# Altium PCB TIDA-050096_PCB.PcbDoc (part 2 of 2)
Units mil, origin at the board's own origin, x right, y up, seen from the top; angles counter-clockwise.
Board outline 3810 x 5470 mil, 4 copper layers (Top Layer, Layer 1, Layer 2, Bottom Layer), stack 70.356 mil thick; 143 components, 52 nets, 310 pads, 92 vias.
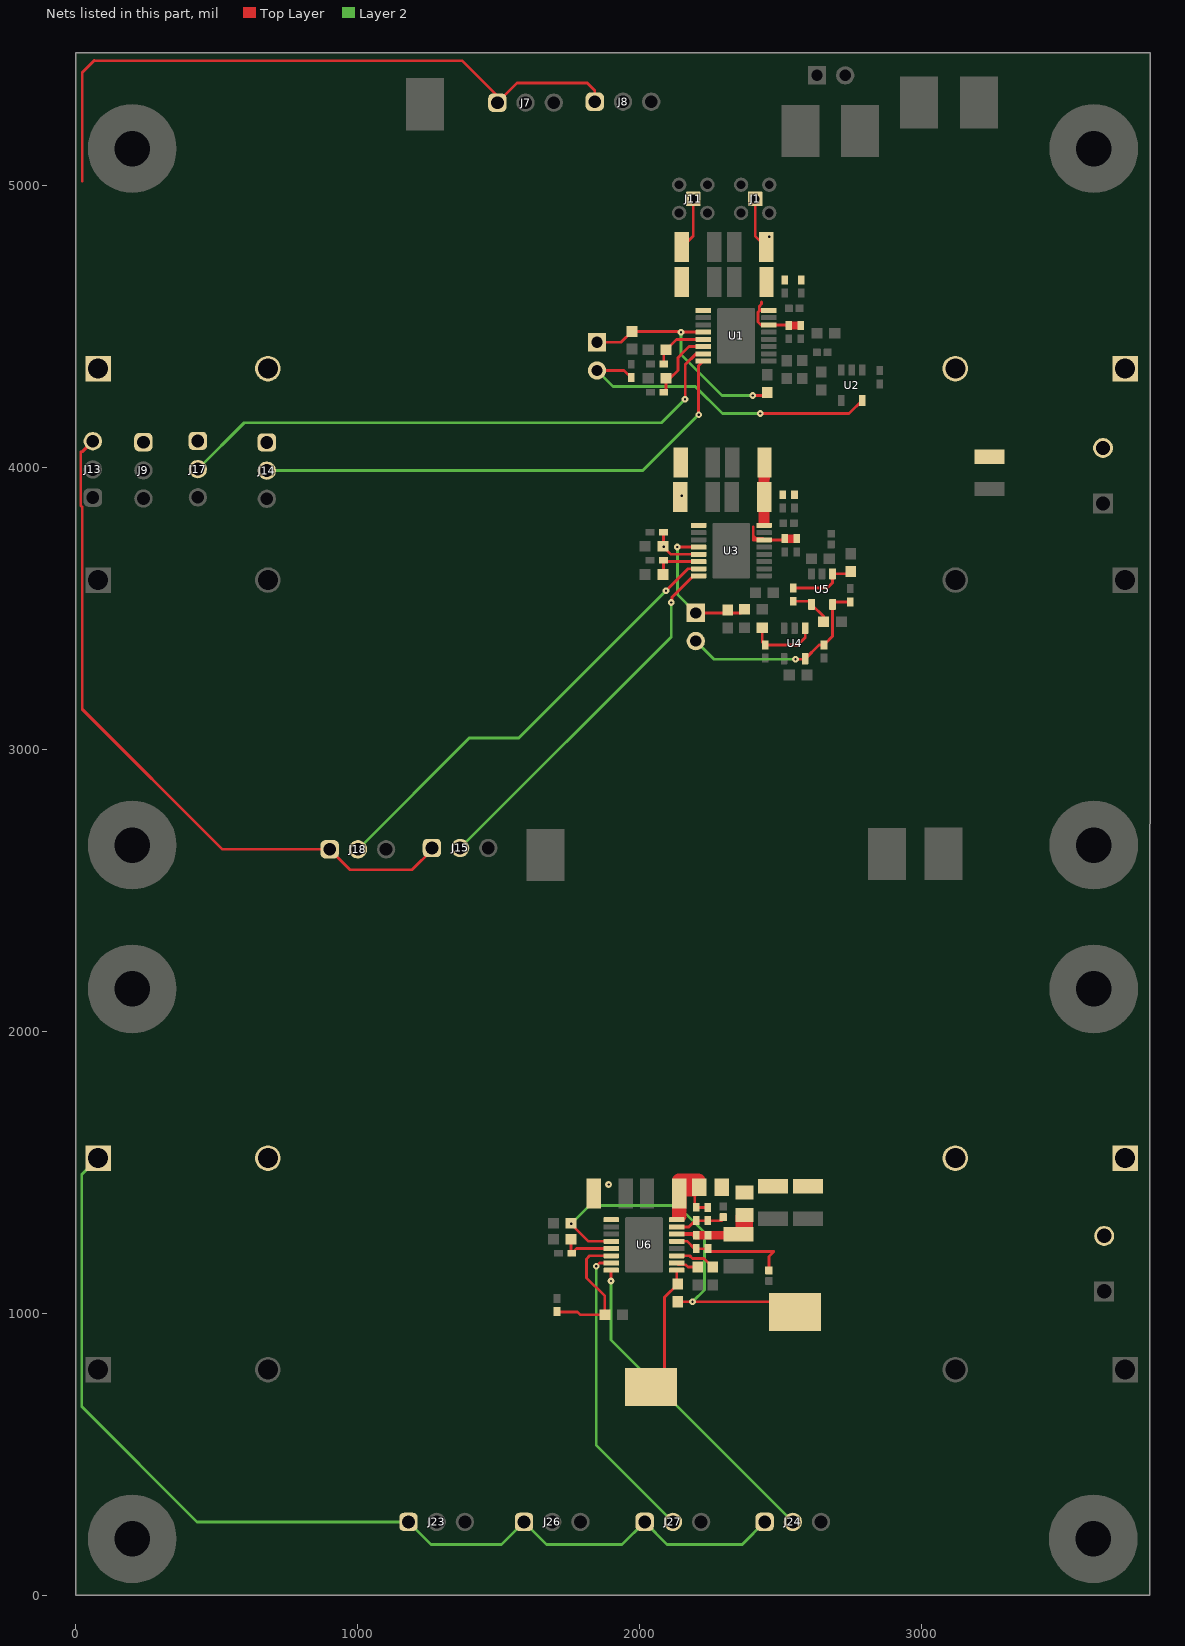
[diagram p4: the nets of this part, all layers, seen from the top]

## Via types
v1: diameter 24, hole 8, Top Layer to Bottom Layer, tented both sides, 47 vias
v2: diameter 19.68, hole 7.87, Top Layer to Bottom Layer, tented both sides, 36 vias
v3: diameter 19.68, hole 7.87, Top Layer to Bottom Layer, 9 vias

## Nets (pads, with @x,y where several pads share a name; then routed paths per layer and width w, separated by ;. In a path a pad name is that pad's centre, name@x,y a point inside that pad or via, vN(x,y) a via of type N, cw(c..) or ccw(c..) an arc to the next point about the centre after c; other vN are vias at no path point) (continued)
NetC11_2: C11.2 R13.1 U4.1 | length 251
  Top Layer w10: R13.1@2434.18,3431.17 2434.18,3380.72 C11.2@2444.63,3370.27 2560.74,3370.27 2586.59,3396.13 U4.1@2586.59,3429.28
NetC25_1: C25.1 R21.2 U5.4 | length 148.4
  Top Layer w10: C25.1@2544.49,3524.76 2598.09,3524.76 U5.4@2608.91,3513.94 2652.22,3470.63 R21.2@2652.22,3452.35
NetC25_2: C25.2 R24.1 U5.1 | length 247.1
  Top Layer w10: C25.2@2544.49,3572.01 2665.34,3572.01 2683.72,3590.38 U5.1@2683.72,3622.2 2740.42,3622.2 R24.1@2748.75,3630.54
NetC27_2: C27.2 R27.2 R34.2 U6.13 | length 433.1
  Top Layer w10: U6.13@2131.23,1254.98 2168.67,1254.98 2195.09,1228.57 2235.09,1228.57 2244.67,1218.98 2475.24,1218.98 2457.86,1201.6 R34.2@2457.86,1152.05
NetC28_2: C28.2 R28.2 R35.2 U6.15 | length 174.7
  Top Layer w10: U6.15@2131.23,1306.16 2173.52,1306.16 2195.1,1327.75 2235.78,1327.75 2236.32,1328.29 2289.29,1328.29 R35.2@2294.58,1333.58
NetC34_2: C34.2 R31.2 U6.6 | length 492.3
  Top Layer w10: R31.2@1706.39,1005.55 1706.39,1004.7 1779.25,1004.7 1789.61,994.33 C34.2@1876.09,994.33 1876.09,1060.66 1811.33,1125.42 1811.33,1192.8 1822.33,1203.8 U6.6@1898.95,1203.8
NetC35_2: C35.2 R32.2 U6.5 | length 206.2
  Top Layer w10: R32.2@1753.09,1206.57 R32.2@1758.71,1212.19 ; C35.2@1756.58,1262.19 1756.58,1214.31 R32.2@1758.71,1212.19 ; U6.5@1898.95,1229.39 1775.91,1229.39 R32.2@1758.71,1212.19
NetR29_2: R29.2 TP10.1 U6.9 | length 454.8
  Top Layer w10: TP10.1@2039.58,738.95 2088.11,787.47 2088.11,1056.7 R29.2@2135.09,1103.68 2131.23,1107.54 U6.9@2131.23,1152.62
NetR30_2: R30.2 U6.11 | length 143.8
  Top Layer w10: U6.11@2131.23,1203.8 2177.26,1203.8 2187.06,1194 2228.19,1194 2258.38,1163.81 R30.2@2258.38,1163.68
NetR33_2: R33.2 U6.10 | length 79.9
  Top Layer w10: U6.10@2131.23,1178.21 2137.33,1172.11 2162.05,1172.11 2170.48,1163.68 R33.2@2205.09,1163.68
SNS_EN1: J14.2 U1.8 | length 1810.9
  Top Layer w10: v1(2208.78,4186.51) 2208.78,4360.28 U1.8@2225.45,4376.95
  Layer 2 w10: J14.2@677.35,3988.19 2010.46,3988.19 v1(2208.78,4186.51)
SNS_EN2: J15.2 U3.8 | length 1325.8
  Top Layer w10: v1(2111.47,3520.76) 2114.15,3523.44 2114.15,3539 2189.74,3614.6 U3.8@2208.44,3614.6
  Layer 2 w10: J15.2@1362.81,2650.02 2111.47,3398.68 v1(2111.47,3520.76)
SNS_EN_Rb: J24.2 U6.8 | length 1160.5
  Top Layer w10: v1(1897.55,1114.37) 1897.55,1151.22 U6.8@1898.95,1152.62
  Layer 2 w10: v1(1897.55,1114.37) 1897.55,905.39 J24.2@2542.93,260
SNS_P: C10.2 R8.2 U1.5 | length 201
  Top Layer w10: R8.2@2085.21,4366.51 2085.21,4408.64 C10.2@2093.09,4416.51 2130.29,4453.72 2188.05,4453.72 U1.5@2225.45,4453.72
SNS_S1: C9.2 R7.2 U1.6 | length 258.2
  Top Layer w10: R7.2@2085.21,4266.51 2093.09,4274.39 C9.2@2093.09,4316.51 2108.22,4316.51 2135.13,4343.43 2135.13,4388.33 2162.55,4415.75 2174.93,4428.13 U1.6@2225.45,4428.13
SNS_S2: C24.2 R19.2 U3.5 | length 188.2
  Top Layer w10: C24.2@2081.94,3719.79 2084.07,3721.92 R19.2@2084.07,3769.79 ; C24.2@2082.93,3719.79 2111.35,3691.37 U3.5@2208.44,3691.37
  other v1: 2084.89,3717.82
SNS_S3: C23.2 R18.2 U3.6 | length 176.9
  Top Layer w10: C23.2@2081.94,3619.79 2084.07,3621.92 R18.2@2084.07,3669.79 2088.08,3665.78 U3.6@2208.44,3665.78
SNS_SEL1: J17.2 U1.7 | length 2033
  Top Layer w10: v1(2160.28,4241.53) 2161.5,4242.75 2161.5,4363.92 2200.11,4402.54 U1.7@2225.45,4402.54
  Layer 2 w10: J17.2@432.84,3993.49 597.42,4158.07 2076.82,4158.07 v1(2160.28,4241.53)
SNS_SEL2: J18.2 U3.7 | length 1620.5
  Top Layer w10: v1(2093.09,3562.42) 2170.85,3640.19 U3.7@2208.44,3640.19 U3.7@2208.24,3640.38
  Layer 2 w10: J18.2@1000.42,2645.17 1395.25,3040 1570.67,3040 v1(2093.09,3562.42)
SNS_SEL_Rb: J27.2 U6.7 | length 1076.9
  Top Layer w10: v1(1845.93,1166.64) 1857.51,1178.21 U6.7@1898.95,1178.21
  Layer 2 w10: v1(1845.93,1166.64) 1845.93,531.6 J27.2@2117.53,260
VCC_1: C8.2 J3.1 R5.1 U1.4 | length 843.1
  Top Layer w10: J3.1@1848.44,4443.21 1933.51,4443.21 C8.2@1972.39,4482.1 2143.76,4482.1 v1(2146.55,4479.31) U1.4@2225.45,4479.31 ; v1(2400.29,4254.52) 2441.09,4254.52 R5.1@2451.59,4265.02
  Layer 2 w10: v1(2146.55,4479.31) 2146.55,4400.19 2292.22,4254.52 v1(2400.29,4254.52)
VCC_1_out: C7.1 J3.2 U2.5 | length 1154.6
  Top Layer w10: J3.2@1848.44,4343.21 1944.39,4343.21 C7.1@1969.44,4318.17 ; v1(2427.57,4190.47) 2742.07,4190.47 U2.5@2788.99,4237.4
  Layer 2 w10: J3.2@1848.44,4343.21 1905.12,4286.53 2196.77,4286.53 2292.83,4190.47 v1(2427.57,4190.47)
VCC_2: C22.1 J12.1 R16.1 U3.4 | length 537.7
  Top Layer w10: v1(2133.28,3716.96) U3.4@2208.44,3716.96 ; J12.1@2198.61,3483.65 2358.04,3483.65 R16.1@2371.19,3496.8 ; C22.1@2302.39,3503.64 C22.1@2312.39,3493.64 ; R16.1@2381.65,3496.8 R16.1@2381.65,3506.8
  Layer 2 w10: v1(2133.28,3716.96) 2133.28,3548.98 J12.1@2198.61,3483.65
VCC_2_out: C20.1 C21.1 J12.2 U4.5 U5.5 | length 725
  Top Layer w10: v1(2552.3,3319.17) 2584.75,3319.17 U4.5@2586.59,3321.01 2635.87,3370.29 C20.1@2653.07,3370.29 2683.72,3400.94 U5.5@2683.72,3513.94 2692.44,3522.66 C21.1@2746.41,3522.66
  Layer 2 w10: J12.2@2198.61,3383.65 2263.09,3319.17 v1(2552.3,3319.17)
VCC_3: C33.1 R29.1 TP9.1 U6.4 | length 1400.5
  Top Layer w10: v1(1756.58,1316.99) 1818.59,1254.98 U6.4@1898.95,1254.98 ; R29.1@2135.09,1040.69 v1(2187.06,1040.69) 2513.48,1040.69 TP9.1@2550,1004.17
  Layer 2 w10: v1(1756.58,1316.99) 1821.23,1381.64 2134.42,1381.64 2229.42,1286.64 2229.42,1083.05 v1(2187.06,1040.69)
VIN: C12.1 C13.1 C14.1 C15.1 J4.1 J4.2 J7.1 J8.1 J9.1 J11.1 J13.3 J14.1 J15.1 J17.1 J18.1 U1.1 U3.1 | length 5050.8
  Top Layer w10: 22.91,5014.41 22.91,5400.39 65.18,5442.66 1371.2,5441.02 1495,5317.22 J7.1@1495,5293.09 1564.51,5362.59 1813.85,5362.59 1840.57,5335.88 J8.1@1840.57,5296.49 ; J13.3@58.8,4092.49 J13.3@60.33,4092.49 22.91,4055.08 17.21,4055.08 17.21,3865.12 22.91,3859.42 22.91,3142.09 519.83,2645.17 J18.1@900.42,2645.17 972.78,2572.8 1192.24,2572.8 1262.81,2643.38 J15.1@1262.81,2650.02 ; C13.1@2149.5,4780.71 2189.66,4820.87 J11.1@2189.66,4951.97
  other v1: 2149.3,3898.96
VIN2: C26.1 J19.1 J19.2 J23.1 J24.1 J26.1 J27.1 U6.1 | length 3695.1
  Layer 2 w10: J19.1@78.82,1550 21.03,1492.21 21.03,668.97 430,260 J23.1@1179.75,260 1259.94,179.82 1509.29,179.82 J26.1@1589.47,260 1669.65,179.82 1937.35,179.82 J27.1@2017.53,260 2097.15,180.38 2363.31,180.38 J24.1@2442.93,260
  other v1: 1889.55,1456.89
VOUT: C2.1 C3.1 C4.1 C5.1 C6.1 C16.1 C17.1 C18.1 C19.1 J1.1 J2.2 J5.1 J5.2 R3.1 R4.1 R14.1 R15.1 U1.14 U1.16 U3.14 U3.16 | length 1040
  Top Layer w10: J1.1@2409.22,4951.97 2409.22,4820.21 C5.1@2449,4780.44 ; U1.14@2431.62,4503.63 2419.54,4515.7 2419.54,4549.63 2423.55,4553.64 ; 2432.12,4585.65 2432.12,4578.91 2423.55,4570.34 2423.55,4553.64 ; U1.14@2457.73,4504.9 2568.39,4504.9 R3.1@2570.36,4502.93 ; U1.16@2457.73,4556.08 2429.14,4556.08 2427.57,4557.65 2423.55,4553.64 ; C16.1@2510.72,3747.23 C16.1@2513.55,3747.23 ; 2536.33,3747.17 R14.1@2556.14,3747.12 ; R14.1@2556.49,3747.47 R14.1@2556.14,3747.12 ; R14.1@2561.06,3747.11 2556.49,3747.12 R14.1@2556.14,3747.12 ; 2402.53,3756.02 2402.53,3788.34 2402.14,3788.73 2402.14,3756.41 2402.53,3756.02 ; 2402.53,3756.02 2402.53,3742.55 U3.14@2440.72,3742.55 ; 2402.53,3756.02 2409.9,3748.65 2434.62,3748.65 U3.14@2440.72,3742.55 ; U3.14@2440.72,3742.55 2551.57,3742.55 R14.1@2556.14,3747.12
  Top Layer w30: C16.1@2517.08,3747.38 R14.1@2551.07,3747.38 ; C3.1@2530.95,4502.84 R3.1@2564.94,4502.84
  Top Layer w40: 2440.39,3805.25 2440.92,3893.89 2441.65,4017.67 C18.1@2441.79,4040.58
  other v1: 2458.84,4817.4
VOUT1_Rb: C28.1 C29.1 R25.1 R28.1 U6.16 | length 430.8
  Top Layer w10: C29.1@2131.23,1415.91 2134.42,1419.11 C29.1@2139.91,1424.59 2154.67,1439.36 C29.1@2155.16,1439.84 ; R25.1@2207.95,1439.84 2195.1,1427 2195.1,1374.99 2235.78,1374.99 C28.1@2236.32,1375.54
  Top Layer w40: 2134.42,1344.17 2134.42,1419.11 C29.1@2134.42,1428.33 ; 2144.84,1342.98 C29.1@2144.84,1427.14
  Top Layer w50: C29.1@2139.78,1471.2 R25.1@2207.33,1471.2 ; C29.1@2145.6,1439.36 2154.67,1439.36 R25.1@2195.09,1439.36
VOUT2_Rb: C27.1 C32.1 R26.1 R27.1 U6.14 | length 336.8
  Top Layer w10: R27.1@2230.32,1280.57 2234.21,1276.69 R27.1@2235.09,1275.81
  Top Layer w15: U6.14@2131.23,1280.57 R27.1@2230.32,1280.57
  Top Layer w30: C27.1@2200.44,1276.69 2234.21,1276.69 C32.1@2300.45,1276.69
  Top Layer w40: C32.1@2359.89,1276.29 R26.1@2359.89,1342.4 ; R26.1@2370.99,1346.82 R26.1@2375.99,1341.82 ; C32.1@2381.18,1282.71 R26.1@2381.18,1340.47
VOUT_Rb: C30.1 C31.1 J20.1 J20.2 J25.2 R25.2 R26.2
pads on no net: H1.0 H2.0 H3.0 H4.0 H5.0 H6.0 H7.0 H8.0 U1.17@2341.59,4466.51 U3.17@2324.58,3704.16 U6.17@2015.09,1242.19

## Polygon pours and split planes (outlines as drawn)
GND on Layer 1 "LAYER_1_GND_P034" (solid, remove dead copper, pour order 34): -1.93,5470 3806.22,5470 3806.22,2480 -1.93,2480
GND2 on Layer 1 "LAYER_1_GND2_P027" (solid, remove dead copper, pour order 27): 5.27,2301.76 3815.27,2301.76 3815.27,3.49 3813.54,1.76 5.27,1.76
VOUT on Top Layer "Top Layer-VOUT" (solid, remove dead copper, pour order 16): 2372.61,3725.99 2869.81,3725.99 3113.82,3970 3800.23,3970 3800.23,4840.12 3809.81,4840 3808.11,4841.7 3808.11,4858.82 3809.81,4860.52 3808.11,4860.52 3808.11,5028.47 2661.33,5028.47 2493.38,4860.52 2385.14,4860.52 2385.14,4604.86 2383.95,4603.68 2409.22,4578.41 2409.22,4545.35 2413.11,4493.21 2744.34,4493.21 2890,4347.56 2890,4276.4 2783.6,4170 2372.61,4170
VIN on Top Layer "Top Layer-VIN" (solid, remove dead copper, pour order 17): 0,4039.1 798.36,4039.1 1079.66,3757.8 2255.45,3757.8 2254.34,3758.9 2254.34,3812.43 2245.13,3812.43 2214.62,3842.93 2214.62,4170 1790.47,4170 1735.16,4225.31 1735.16,4470.17 1784.14,4519.15 2273.52,4519.15 2273.52,4565.53 2221.51,4617.54 2221.51,4859.74 2221.07,4860.18 2218.05,4857.16 2101.78,4857.16 1938.94,5020 0,5020 0,4838.37
GND on Top Layer "TOP_LAYER_GND_P043" (solid, remove dead copper, pour order 43): -1.77,5470 3806.37,5470 3806.37,2480 -1.77,2480
GND2 on Top Layer "TOP_LAYER_GND2_P044" (solid, remove dead copper, pour order 44): 0,2300 3810,2300 3810,1.73 3808.27,0 0,0
VOUT_Rb on Top Layer "TOP_LAYER_VOUT_RB_P026" (solid, remove dead copper, pour order 26): 3803.66,1200 3803.66,2300 2259.96,2300 2259.96,1394.21 2266.88,1401.13 2658.08,1401.13 2859.21,1200 3808.24,1200
VIN2 on Top Layer "TOP_LAYER_VIN2_P021" (solid, remove dead copper, pour order 21): 0,1300 22.58,1322.58 1907,1322.58 1907,2300 -3.66,2300 -3.66,1300
no net on Top Layer "TOP_LAYER_NONET_P040" (solid, remove dead copper, pour order 40): 1570.49,3741.6 1570.49,3711.6 1570.49,3525.83 1653.94,3525.83 1730.42,3602.31 1730.42,3741.6
VOUT on Layer 2 "Top Layer-VOUT" (solid, remove dead copper, pour order 4): 2372.61,3652.12 2795.94,3652.12 3800.23,3652.12 3800.23,4840.12 3809.81,4840 3808.11,4841.7 3808.11,4858.82 3809.81,4860.52 3808.11,4860.52 3808.11,5028.47 2643.53,5028.47 2372.61,4757.55 2372.61,4592.33 2372.61,4508.73 2372.61,4170
VIN on Layer 2 "Top Layer-VIN" (solid, remove dead copper, pour order 32): 0,4039.1 798.36,4039.1 1079.66,3757.8 2255.45,3757.8 2254.34,3758.9 2254.34,3812.43 2245.13,3812.43 2214.62,3842.93 2214.62,4170 1790.47,4170 2221.51,4170 2221.51,4617.54 2221.51,4859.74 2221.07,4860.18 2218.05,4857.16 2101.78,4857.16 1938.94,5020 0,5020 0,4838.37
GND on Layer 2 "LAYER_2_GND_P045" (solid, remove dead copper, pour order 45): -1.93,5470 3806.22,5470 3806.22,2480 -1.93,2480
GND2 on Layer 2 "LAYER_2_GND2_P035" (solid, remove dead copper, pour order 35): 0,2300 3810,2300 3810,1.73 3808.27,0 0,0
VIN2 on Layer 2 "LAYER_2_VIN2_P008" (solid, remove dead copper, pour order 8): 0,1300 22.58,1322.58 1907,1322.58 1907,2300 -3.66,2300 -3.66,1300
VOUT_Rb on Layer 2 "LAYER_2_VOUT_RB_P007" (solid, remove dead copper, pour order 7): 3803.66,1200 3803.66,2300 2259.96,2300 2259.96,1394.21 2266.88,1401.13 2658.08,1401.13 2859.21,1200 3808.24,1200
GND on Bottom Layer "BOTTOM_LAYER_GND_P000" (solid, remove dead copper, pour order 0): 0,5470 3808.14,5470 3808.14,2480 0,2480
GND2 on Bottom Layer "BOTTOM_LAYER_GND2_P001" (solid, remove dead copper, pour order 1): 0,2300 3810,2300 3810,1.73 3808.27,0 0,0

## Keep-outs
Keep-Out Layer:
  text ".Layer_Name" at 25.82,-858.49 h60

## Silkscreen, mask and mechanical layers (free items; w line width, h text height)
Top Overlay:
  lines w10: 502.52,3993.49 522.21,3993.49 ; 747.67,3982.6 767.35,3982.6 ; 1000.42,2711.24 1000.42,2798.44 ; 1362.81,2716.1 1362.81,2803.29 ; 2117.53,80 2117.53,200 ; 2544.94,79.38 2544.94,199.38
  text "EN1" at 1575.82,5456.36 h30 r270
  text "VIN" at 1470.66,5453.7 h30 r270
  text "GND" at 1672.13,5453.7 h30 r270
  text "VIN" at 1818.84,5447.1 h30 r270
  text "EN2" at 1920.38,5447.1 h30 r270
  text "GND" at 2020.31,5447.1 h30 r270
  text "GND" at 1195.65,5156.49 h60 r270
  text "ILIM1" at 2960,5150 h60 r270
  text "ILIM2" at 3170,5150 h60 r270
  text "ERR1" at 2532.39,5056.57 h60 r270
  text "ERR2" at 2739.19,5056.57 h60 r270
  text "VIN" at 290,4430.09 h60
  text "VOUT" at 3320,4390 h60
  text "1.2A max" at 3190,4284.01 h60
  text "SNS_SEL1" at 537.35,4102.75 h30 r270
  text "SNS_EN1" at 780,4089.1 h30 r270
  text "EN4" at 127.08,4033.65 h30 r270
  text "EN3" at 300,4033.65 h30 r270
  text "GND" at 3320,3551.65 h60
  text "GND" at 300,3474.33 h60
  text "ILIM3" at 2846.88,3070 h60 r270
  text "ILIM4" at 3046.88,3070 h60 r270
  text "GND" at 1628.19,2940 h60 r270
  text "SNS_EN2" at 1262.81,2820.02 h30
  text "SNS_SEL2" at 890.42,2815.17 h30
  text "VIN" at 1242.81,2800.02 h30 r270
  text "GND" at 1442.81,2800.02 h30 r270
  text "VIN" at 880.42,2791.24 h30 r270
  text "GND" at 1080.42,2791.24 h30 r270
  text "0.5A max (ballast technique)" at 2759.84,1770 h30
  text "VOUT" at 3300,1520 h60
  text "VIN" at 290,1507.56 h60
  text "GND" at 290,760 h60
  text "GND" at 3310,760 h60
  text "EN1_Rb" at 1252.93,200 h30 r270
  text "EN2_Rb" at 1666.46,200 h30 r270
  text "VIN2" at 1994.23,200 h30 r270
  text "GND" at 2199.8,200 h30 r270
  text "VIN2" at 2419.78,200 h30 r270
  text "GND" at 2622.93,200 h30 r270
  text "VIN2" at 1154.51,180.38 h30 r270
  text "VIN2" at 1567.99,179.82 h30 r270
  text "GND" at 1774.46,180.38 h30 r270
  text "GND" at 1357.1,170 h30 r270
  text "SNS_SEL_Rb" at 1967.53,20 h30
  text "SNS_SEL_Rb" at 2397.37,20 h30
Bottom Overlay:
  text "Vout" at 2372.23,5325.09 h60 r270
  text "Vin" at 2138.5,5269.56 h60 r270
Top Paste:
  text ".Layer_Name" at 25.82,-858.49 h60
Bottom Paste:
  text ".Layer_Name" at 25.82,-858.49 h60
Top Solder:
  text ".Layer_Name" at 25.82,-858.49 h60
  text ".Layer_Name" at 25.82,-858.49 h60
Bottom Solder:
  text ".Layer_Name" at 25.82,-858.49 h60
Drill Guide:
  text ".Layer_Name" at 25.82,-858.49 h60
M1 Board Outline:
  the board outline again, w10
  text ".Layer_Name" at 25.82,-858.49 h60
M2 Board Dimensions:
  rectangle: -551.18,-275 -426.18,-150
  rectangle: -426.18,-400 -51.18,-275
  lines w7: -551.18,-275 448.82,-275 ; -426.18,-400 -426.18,-150 ; -301.18,-400 -301.18,-150 ; -51.18,-400 -51.18,-150 ; 198.82,-400 198.82,-150 ; -551.18,-400 448.82,-400 448.82,-150 -551.18,-150 -551.18,-400
  text ".Layer_Name" at 25.82,-858.49 h60
M3 3D STEP Top:
  text ".Layer_Name" at 25.82,-858.49 h60
M4 3D STEP Bottom:
  text ".Layer_Name" at 25.82,-858.49 h60
M5 Assembly Top:
  lines w10: -843.18,-930.17 5756.82,-930.17 ; -843.18,-726.83 5758.82,-726.83 ; -843.18,-523.5 -843.18,-1133.5 3161.82,-1133.5 5758.82,-1133.5 5758.82,-523.5 -842.68,-523.5 -842.68,-1133.5 732.82,-1133.5 ; 1621.82,-1133.5 1621.82,-523.5 ; 2888.82,-726.83 2888.82,-523.5 ; 3728.82,-726.83 3728.82,-523.5 ; 4350.82,-1140 4350.82,-937.17
  text "COMPONENTS MARKED 'DNP' SHOULD NOT BE POPULATED." at 602.32,-318.5 h60
  text "ASSEMBLY VARIANT:" at 601.82,-434 h60
  text ".VariantName" at 1637.82,-434 h60
  text "PCB VIEWED FROM TOP SIDE" at -779.68,-655.67 h60
  text "BOARD #:" at 1696.82,-655.67 h60
  text ".PRJ_Number" at 2242.32,-655.67 h60
  text "REV:" at 3086.82,-655.67 h60
  text ".PCB_Rev" at 3378.32,-655.67 h60
  text "SVN REV:" at 3924.82,-655.67 h60
  text ".VersionControl_RevNumber" at 4430.82,-655.67 h60
  text "TID #:" at 1696.82,-859 h60
  text ".TID" at 2242.32,-859 h60
  text "PLOT NAME =" at -779.68,-1064.34 h60
  text ".plot_File_Name" at 25.82,-1064.34 h60
  text "GENERATED    :" at 1698.82,-1064.34 h60
  text ".Print_Date" at 2568.32,-1064.34 h60
  text ".Print_Time" at 3297.32,-1064.34 h60
  text "TEXAS INSTRUMENTS" at 4561.82,-1064.34 h60
M6 Assembly Bottom:
  lines w10: -843.68,-727.33 5758.32,-727.33 ; -841.68,-930.67 5758.32,-930.67 ; 564.32,-1140.5 564.32,-937.67 ; 1186.32,-727.33 1186.32,-524 ; 2026.32,-727.33 2026.32,-524 ; 3293.32,-1134 3293.32,-524 ; 4182.32,-1134 5757.82,-1134 5757.82,-524 -843.68,-524 -843.68,-1134 1753.32,-1134 5758.32,-1134 5758.32,-524
  text "COMPONENTS MARKED 'DNP' SHOULD NOT BE POPULATED." at 5550.82,-318 h60
  text ".VariantName" at 4506.82,-434 h60
  text "ASSEMBLY VARIANT:" at 5545.82,-434 h60
  text ".VersionControl_RevNumber" at 484.32,-656.17 h60
  text "SVN REV:" at 990.32,-656.17 h60
  text ".PCB_Rev" at 1536.82,-656.17 h60
  text "REV:" at 1828.32,-656.17 h60
  text ".PRJ_Number" at 2672.82,-656.17 h60
  text "BOARD #:" at 3218.32,-656.17 h60
  text "PCB VIEWED FROM BOTTOM SIDE" at 5694.82,-656.17 h60
  text ".TID" at 2672.82,-859.5 h60
  text "TID #:" at 3218.32,-859.5 h60
  text "TEXAS INSTRUMENTS" at 353.32,-1064.84 h60
  text ".Print_Time" at 1617.82,-1064.84 h60
  text ".Print_Date" at 2346.82,-1064.84 h60
  text "GENERATED    :" at 3216.32,-1064.84 h60
  text ".plot_File_Name" at 4889.32,-1064.84 h60
  text "PLOT NAME =" at 5694.82,-1064.84 h60
M9 Title Sheet:
  drawing of 57 lines, arcs and shapes, not listed
  text "1" at 188.66,8036.5 h70
  text "2" at 2684.32,8036.5 h70
  text "3" at 5173.66,8036.5 h70
  text "4" at 7680.33,8036.5 h70
  text "5" at 10179.32,8036.5 h70
  text "6" at 12684.32,8036.5 h70
  text "A" at -967.68,6893.5 h70
  text "A" at 13832.32,6893.5 h70
  text "B" at -967.68,4513.5 h70
  text "B" at 13832.32,4513.5 h70
  text "C" at -967.68,2138.5 h70
  text "C" at 13832.32,2138.5 h70
  text "PROJECT TITLE:" at 10792.32,277.5 h45
  text ".PRJ_Title" at 10842.32,144.17 h70
  text "DESIGNED FOR:" at 10792.32,-23.5 h45
  text ".PRJ_Customer" at 10842.32,-163.5 h70
  text "D" at -967.68,-231.5 h70
  text "D" at 13832.32,-231.5 h70
  text "FILE NAME:" at 10792.32,-323.5 h45
  text ".PCB_File_Name_No_Path" at 10842.32,-443.5 h70
  text "Texas Instruments (TI) and/or its licensors do not warrant the accuracy or completeness of this specification" at 5822.82,-605.34 h45
  text "ENGINEER:" at 10792.32,-613.5 h45
  text "LAYOUT BY:" at 12297.32,-613.5 h45
  text "or any information contained therein. TI and/or its licensors do not warrant that this design will meet" at 5777.83,-718 h45
  text ".PRJ_Engineer" at 10842.32,-768.49 h70
  text ".PCB_Layout" at 12347.82,-768.49 h70
  text "the specifications, will be suitable for your application or fit for any particular purpose, or will operate in" at 5777.83,-830.67 h45
  text ".Layer_Name" at 25.82,-858.49 h60
  text "ALTIUM DESIGNER VERSION:" at 12297.32,-923.5 h45
  text "an implementation. TI and/or its licensors do not warrant that the design is production worthy. You should" at 5777.83,-943.33 h45
  text "completely validate and test your design implementation to confirm the system functionality for your application." at 5822.82,-1056 h45
  text ".print_Scale" at 10842.32,-1056.83 h70
  text ".Application_BuildNumber" at 12347.82,-1056.83 h70
  text "1" at 188.66,-1263.5 h70
  text "2" at 2684.32,-1263.5 h70
  text "3" at 5173.66,-1263.5 h70
  text "4" at 7680.33,-1263.5 h70
  text "5" at 10179.32,-1263.5 h70
  text "6" at 12684.32,-1263.5 h70
M10 Fab Notes:
  drawing of 189 lines, arcs and shapes, not listed
  text "DESIGN INFORMATION" at 11830.84,6356.17 h60
  text "MIN. TRACK WIDTH:" at 11186.28,6224.05 h60
  text "8" at 12282.52,6224.05 h60
  text "MIL" at 12437.28,6224.05 h60
  text "MIN. CLEARANCE:" at 11186.28,6099.92 h60
  text "0.2" at 12222.52,6099.93 h60
  text "mm" at 12437.28,6099.92 h60
  text "MIN. VIA PAD SIZE:" at 11186.28,5975.8 h60
  text "24" at 12252.53,5975.8 h60
  text "MIL" at 12437.28,5975.8 h60
  text "0.05mm (2MIL)" at 11881.28,5845.9 h60
  text "MINIMUM ANNULAR RING" at 10857.05,5837.67 h60
  text "EXTERNAL" at 12589.28,5837.67 h60
  text "PER" at 11057.05,5727.55 h60
  text "IPC-D-275 CLASS 2 LEVEL C" at 11277.05,5727.54 h60
  text "MIL, HOLES" at 12765.28,5627.07 h60
  text "+/-" at 12372.82,5618.48 h60
  text "+/-" at 13226.82,5618.48 h60
  text "REGISTRATION TOLERANCES:" at 10857.05,5617.42 h60
  text "METAL" at 12056.82,5617.42 h60
  text "5" at 12633.02,5617.42 h60
  text "3" at 13466.02,5617.42 h60
  text "MIL" at 13582.28,5617.42 h60
  text "HOLE SIZE TOLERANCE (UNLESS OTHERWISE SPECIFIED):" at 10857.05,5519.1 h60
  text "+/-" at 13226.82,5516.23 h60
  text "3" at 13466.02,5515.17 h60
  text "MIL" at 13582.28,5515.17 h60
  text "MATERIAL:" at 10782.28,5377.52 h60
  text "FR-4 High Tg" at 11768.72,5249 h60
  text "X" at 11624.28,5241.01 h60
  text "FR-408" at 11203.28,5236.49 h60
  text "OTHER" at 12691.28,5236.49 h60
  text "62 MIL (1.6mm) +/-10%" at 11523.38,5093.46 h60
  text "X" at 11403.28,5091.01 h60
  text "THICKNESS:" at 10857.05,5085.24 h60
  text "OTHER" at 12808.28,5085.24 h60
  text "TOLERANCE:" at 10857.05,4946.92 h60
  text "X" at 11705.28,4946.92 h60
  text "ANSI IPC-6012 TYPE 3 CLASS 2" at 11883.29,4946.92 h60
  text "OTHER +/-" at 11883.28,4802.73 h60
  text "BOW & TWIST:" at 10857.05,4657.54 h60
  text "X" at 11705.28,4657.54 h60
  text "ANSI IPC-6012 TYPE 3 CLASS 2" at 11883.29,4657.54 h60
  text "OTHER +/-" at 11883.28,4510.85 h60
  text "DRILLING:" at 10782.28,4380.23 h60
  text "NC_DRILL FILES" at 12543.28,4275.04 h60
  text "REFERENCE:" at 10857.05,4271.1 h60
  text "X" at 11514.28,4271.01 h60
  text "AS SHOWN" at 11692.28,4271.1 h60
  text "X" at 12415.28,4271.1 h60
  text "OTHER" at 12841.28,4128.85 h60
  text "PTH COPPER THICKNESS:" at 10856.72,4125.32 h60
  text "X" at 11995.96,4125.32 h60
  text "20-30 um" at 12123.96,4125.32 h60
  text "BOARD FINISH:" at 10782.28,3977.73 h60
  text "SILKSCREEN:" at 10937.5,3867.6 h60
  text "X" at 11895.28,3867.6 h60
  text "TOP" at 12012.28,3867.6 h60
  text "X" at 12405.28,3867.6 h60
  text "BOTTOM" at 12523.28,3867.6 h60
  text "SILKSCREEN COLOR:" at 10937.5,3712.41 h60
  text "X" at 11894.28,3712.41 h60
  text "WHITE" at 12012.28,3712.41 h60
  text "OTHER" at 12523.28,3712.41 h60
  text "X" at 12025.28,3568.96 h60
  text "GREEN" at 12143.28,3568.96 h60
  text "OTHER" at 12761.28,3568.96 h60
  text "SOLDER RESIST COLOR:" at 10937.5,3562.1 h60
  text "X" at 12025.28,3414.71 h60
  text "MATTE" at 12143.28,3414.71 h60
  text "SEMI-GLOSS" at 12760.82,3414.07 h60
  text "IMMERSION GOLD (ENIG)" at 11843.28,3241.94 h60
  text "ENEPIG" at 13180.82,3234.72 h60
  text "SURFACE FINISH:" at 10782.28,3233.72 h60
  text "X" at 11665.28,3233.72 h60
  text "IMM. TIN/SILVER OR EQUIV" at 11111.82,3096.4 h60
  text "OTHER" at 12543.28,3092.47 h60
  text "ARRAY/PANEL:" at 10782.28,2937.09 h60
  text "CUT AND TRIM PER M1 BOARD OUTLINE" at 11843.28,2928.87 h60
  text "X" at 11665.28,2792.9 h60
  text "TAB ROUTE" at 11843.28,2792.9 h60
  text "V. SCORE" at 12709.28,2792.9 h60
  text "CERTIFICATION:" at 10782.28,2663.77 h60
  text "MATERIALS AND WORKMANSHIP FOR ALL PCBS" at 11507.28,2663.77 h60
  text "TO MEET OR EXCEED THE REQUIREMENTS OF:" at 11507.28,2569.71 h60
  text "X" at 11144.79,2441.08 h60
  text "ANSI IPC-A-600F CLASS ->" at 11272.78,2441.08 h60
  text "X" at 12920.79,2441.08 h60
  text "2" at 13030.78,2441.08 h60
  text "1" at 12715.78,2439.58 h60
  text "3" at 13384.78,2439.58 h60
  text "-Tab Route Line / 200mil spacing between copper planes" at 3910.31,2330 h72.83
  text "X" at 11956.79,2293.39 h60
  text "RoHS" at 12084.78,2293.39 h60
  text "OTHER" at 12729.18,2293.39 h60
  text "PER ORDER" at 13126.24,2293.39 h60
  text "ALL BOARDS MUST MEET OR EXCEED UL94-V0 REQUIREMENTS." at 10809.82,2139.57 h60
  text "PCB MUST BEAR THE UL94V-0 UL REGISTERED MATERIAL ID NUMBER" at 10809.82,2023.5 h60
  text "ADDITIONAL REQUIREMENTS:" at 10782.28,1854.08 h60
  text "MICROSECTION:" at 10857.05,1746.95 h60
  text "YES" at 11762.78,1746.95 h60
  text "REQUIRED" at 12624.28,1602.62 h60
  text "BARE BOARD ELEC. TEST:" at 10857.05,1599.76 h60
  text "NONE" at 12162.78,1599.76 h60
  text "X" at 12506.28,1599.76 h60
  text "PER ORDER" at 13216.28,1599.76 h60
  text "XX MIL VIAS REQUIRE NON-CONDUCTIVE FILL AND PLANARIZE" at 11025.2,1394.82 h59
  text "XX MIL VIAS REQUIRE CONDUCTIVE FILL AND PLANARIZE" at 11033.2,1290.84 h60
  text "OUTER XX MIL TRACES REQUIRE 50 OHM SINGLE-ENDED IMPEDANCE" at 11032.21,1127.46 h58
  text "LAYER 2 & 3 (INNER LAYERS) XX MIL WIDE, XX MIL SPACE / TRACES REQUIRE 100 OHM DIFFERENTIAL IMPEDANCE" at 11024.21,891.74 h60
  text ".Layer_Name" at 25.82,-858.49 h60
M11 Gerber Information:
  lines w10: -843.18,-930.17 5756.82,-930.17 ; -843.18,-726.83 5758.82,-726.83 ; -843.18,-523.5 -843.18,-1133.5 3161.82,-1133.5 5758.82,-1133.5 5758.82,-523.5 -842.68,-523.5 -842.68,-1133.5 732.82,-1133.5 ; 1621.82,-1133.5 1621.82,-523.5 ; 2888.82,-726.83 2888.82,-523.5 ; 3728.82,-726.83 3728.82,-523.5 ; 4350.82,-1140 4350.82,-937.17
  text "ALL ARTWORK VIEWED FROM TOP SIDE" at -779.68,-655.67 h60
  text "BOARD #:" at 1696.82,-655.67 h60
  text ".PRJ_Number" at 2242.32,-655.67 h60
  text "REV:" at 3086.82,-655.67 h60
  text ".PCB_Rev" at 3378.32,-655.67 h60
  text "SVN REV:" at 3924.82,-655.67 h60
  text ".VersionControl_RevNumber" at 4430.82,-655.67 h60
  text "LAYER NAME =" at -779.68,-858.49 h60
  text "TID #:" at 1696.82,-859 h60
  text ".TID" at 2242.32,-859 h60
  text "PLOT NAME =" at -779.68,-1064.34 h60
  text ".plot_File_Name" at 25.82,-1064.34 h60
  text "GENERATED    :" at 1698.82,-1064.34 h60
  text ".Print_Date" at 2568.32,-1064.34 h60
  text ".Print_Time" at 3297.32,-1064.34 h60
  text "TEXAS INSTRUMENTS" at 4561.82,-1064.34 h60
M12 Stackup:
  drawing of 295 lines, arcs and shapes, not listed
  text "Layer" at 9270.41,7874.94 h60
  text "Name" at 9680.33,7874.94 h60
  text "Material" at 10610.07,7874.94 h60
  text "Thickness" at 11469.84,7874.94 h60
  text "Constant" at 12119.67,7874.94 h60
  text "Board Layer Stack" at 12689.53,7874.94 h60
  text "Top Overlay" at 9680.33,7754.94 h60
  text "Top Solder" at 9680.33,7634.94 h60
  text "Solder Resist" at 10610.07,7634.94 h60
  text "0.40mil" at 11469.84,7634.94 h60
  text "3.5" at 12119.67,7634.94 h60
  text "1" at 9270.41,7514.94 h60
  text "Top Layer" at 9680.33,7514.94 h60
  text "1.40mil" at 11469.84,7514.94 h60
  text "Dielectric 1" at 9680.33,7394.94 h60
  text "PP-006" at 10610.07,7394.94 h60
  text "2.80mil" at 11469.84,7394.94 h60
  text "4.1" at 12119.67,7394.94 h60
  text "2" at 9270.41,7274.94 h60
  text "Layer 1" at 9680.33,7274.94 h60
  text "CF-004" at 10610.07,7274.94 h60
  text "1.38mil" at 11469.84,7274.94 h60
  text "Dielectric1" at 9680.33,7154.94 h60
  text "FR-4" at 10610.07,7154.94 h60
  text "59.20mil" at 11469.84,7154.94 h60
  text "4.8" at 12119.67,7154.94 h60
  text "3" at 9270.41,7034.94 h60
  text "Layer 2" at 9680.33,7034.94 h60
  text "CF-004" at 10610.07,7034.94 h60
  text "1.38mil" at 11469.84,7034.94 h60
  text "Dielectric 2" at 9680.33,6914.94 h60
  text "PP-006" at 10610.07,6914.94 h60
  text "2.80mil" at 11469.84,6914.94 h60
  text "4.1" at 12119.67,6914.94 h60
  text "4" at 9270.41,6794.94 h60
  text "Bottom Layer" at 9680.33,6794.94 h60
  text "1.40mil" at 11469.84,6794.94 h60
  text "Bottom Solder" at 9680.33,6674.94 h60
  text "Solder Resist" at 10610.07,6674.94 h60
  text "0.40mil" at 11469.84,6674.94 h60
  text "3.5" at 12119.67,6674.94 h60
  text "Bottom Overlay" at 9680.33,6554.94 h60
  text ".Layer_Name" at 25.82,-858.49 h60
M13 Component Bodies Top:
  text ".Layer_Name" at 25.82,-858.49 h60
M14 Component Bodies Bottom:
  text ".Layer_Name" at 25.82,-858.49 h60
M15 Courtyards Top:
  text ".Layer_Name" at 25.82,-858.49 h60
M16 Courtyards Bottom:
  text ".Layer_Name" at 25.82,-858.49 h60
Drill Drawing:
  circle w10: c5914.9,7565.57 r16.58
  circle w10: c5914.9,7565.57 r27.63
  circle w10: c5914.9,6819.65 r27.63
  lines w10: 5887.27,6916.34 5887.27,6930.15 5901.08,6943.97 5887.27,6957.78 5887.27,6971.59 5901.08,6971.59 5914.9,6957.78 5928.71,6971.59 5942.52,6971.59 5942.52,6957.78 5928.71,6943.97 5942.52,6930.15 5942.52,6916.34 5928.71,6916.34 5914.9,6930.15 5901.08,6916.34 5887.27,6916.34 ; 5887.27,7068.29 5914.9,7040.66 5942.52,7068.29 5914.9,7095.91 5887.27,7068.29 ; 5887.27,7164.98 5942.52,7164.98 5942.52,7220.23 5887.27,7220.23 5887.27,7164.98 ; 5887.27,7303.11 5901.08,7303.11 5901.08,7289.3 5928.71,7289.3 5928.71,7303.11 5942.52,7303.11 5942.52,7330.74 5928.71,7330.74 5928.71,7344.55 5901.08,7344.55 5901.08,7330.74 5887.27,7330.74 5887.27,7303.11 ; 5887.27,7413.62 5942.52,7413.62 5942.52,7468.87 5887.27,7468.87 5887.27,7413.62 ; 5887.27,7662.26 5914.9,7676.07 5942.52,7662.26 5928.71,7689.89 5942.52,7717.51 5914.9,7703.7 5887.27,7717.51 5901.08,7689.89 5887.27,7662.26 ; 5898.32,7424.67 5931.47,7424.67 5931.47,7457.82 5898.32,7457.82 5898.32,7424.67
  lines w12: 5837.18,6754.73 9068.67,6754.73 ; 5837.18,7749.29 9068.67,7749.29 ; 6175.04,6630.41 6175.04,7873.61 ; 6507.04,6630.41 6507.04,7873.61 ; 7143.61,6630.41 7143.61,7873.61 ; 7402.75,6630.41 7402.75,7873.61 ; 7777.9,6630.41 7777.9,7873.61 ; 8502.24,6630.41 8502.24,7873.61 ; 5837.18,6630.41 9068.67,6630.41 9068.67,7873.61 5837.18,7873.61 5837.18,6630.41
  text "Symbol" at 5911.77,7786.58 h72
  text "Quantity" at 6212.34,7786.58 h72
  text "Finished Hole Size" at 6544.34,7786.58 h72
  text "Plated" at 7180.9,7786.58 h72
  text "Hole Type" at 7440.04,7786.58 h72
  text "Drill Layer Pair" at 7815.2,7786.58 h72
  text "Hole Tolerance" at 8539.53,7786.58 h72
  text "45" at 6212.34,7662.26 h60
  text "7.87mil (0.200mm)" at 6544.34,7662.26 h60
  text "PTH" at 7180.9,7662.26 h60
  text "Round" at 7440.04,7662.26 h60
  text "Top Layer - Bottom Layer" at 7815.2,7662.26 h60
  text "47" at 6212.34,7537.94 h60
  text "8.00mil (0.203mm)" at 6544.34,7537.94 h60
  text "PTH" at 7180.9,7537.94 h60
  text "Round" at 7440.04,7537.94 h60
  text "Top Layer - Bottom Layer" at 7815.2,7537.94 h60
  text "10" at 6212.34,7413.62 h60
  text "31.50mil (0.800mm)" at 6544.34,7413.62 h60
  text "PTH" at 7180.9,7413.62 h60
  text "Round" at 7440.04,7413.62 h60
  text "Top Layer - Bottom Layer" at 7815.2,7413.62 h60
  text "6" at 6212.34,7289.3 h60
  text "40.00mil (1.016mm)" at 6544.34,7289.3 h60
  text "PTH" at 7180.9,7289.3 h60
  text "Round" at 7440.04,7289.3 h60
  text "Top Layer - Bottom Layer" at 7815.2,7289.3 h60
  text "36" at 6212.34,7164.98 h60
  text "45.28mil (1.150mm)" at 6544.34,7164.98 h60
  text "PTH" at 7180.9,7164.98 h60
  text "Round" at 7440.04,7164.98 h60
  text "Top Layer - Bottom Layer" at 7815.2,7164.98 h60
  text "4" at 6212.34,7040.66 h60
  text "51.18mil (1.300mm)" at 6544.34,7040.66 h60
  text "PTH" at 7180.9,7040.66 h60
  text "Round" at 7440.04,7040.66 h60
  text "Top Layer - Bottom Layer" at 7815.2,7040.66 h60
  text "16" at 6212.34,6916.34 h60
  text "70.87mil (1.800mm)" at 6544.34,6916.34 h60
  text "PTH" at 7180.9,6916.34 h60
  text "Round" at 7440.04,6916.34 h60
  text "Top Layer - Bottom Layer" at 7815.2,6916.34 h60
  text "8" at 6212.34,6792.02 h60
  text "125.98mil (3.200mm)" at 6544.34,6792.02 h60
  text "PTH" at 7180.9,6792.02 h60
  text "Round" at 7440.04,6792.02 h60
  text "Top Layer - Bottom Layer" at 7815.2,6792.02 h60
  text "172 Total" at 6212.34,6667.7 h60
  text ".Layer_Name" at 25.82,-858.49 h60
M17 Embedded Cavity:
  text ".Layer_Name" at 25.82,-858.49 h60
M18 Embedded Assembly:
  text ".Layer_Name" at 25.82,-858.49 h60
M19 Embedded Keepout:
  text ".Layer_Name" at 25.82,-858.49 h60
Route Tool Path:
  lines w20: 171.52,2400 171.69,2400 ; 221.7,2400 221.87,2400 ; 1012.87,2400 1013.04,2400 ; 1063.05,2400 1063.22,2400 ; 1849.91,2400 1850.08,2400 ; 1900.09,2400 1900.26,2400 ; 2691.2,2400 2691.38,2400 ; 2741.39,2400 2741.56,2400 ; 3539.82,2400 3539.99,2400 ; 3590,2400 3590.17,2400
  lines w100: -5.75,2400.18 77.1,2400 ; 323.21,2400 913.21,2400 ; 1161.66,2400 1751.66,2400 ; 1998.92,2400 2588.92,2400 ; 2840,2400 3430,2400 ; 3682.3,2400 3811.82,2400

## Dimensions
-551.18,-400 to 448.82,-400 on M2 Board Dimensions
